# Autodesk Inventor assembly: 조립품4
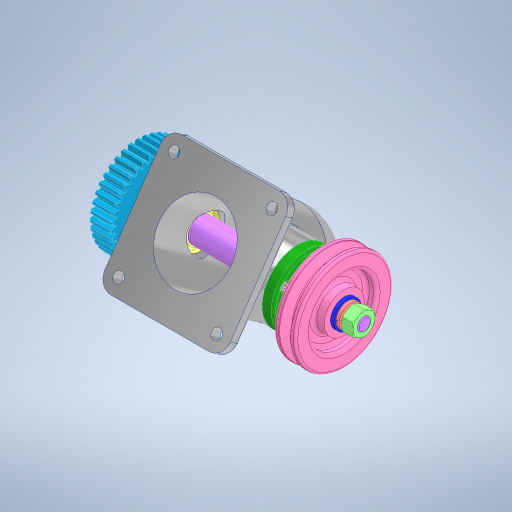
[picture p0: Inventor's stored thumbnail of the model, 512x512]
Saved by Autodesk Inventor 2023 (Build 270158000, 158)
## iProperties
Created: 2025-04
Part Number: 조립품4
Document SubType Name: Assembly
Designer: user
Author: user
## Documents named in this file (14)
- C:\Users\user\Desktop\750406V1015 유정현\OldVersions\조립품4.iam
- C:\Users\user\Desktop\750406V1015 유정현\본체.ipt
- C:\Users\user\Desktop\750406V1015 유정현\깊은 홈 볼 베어링 6203.ipt
- C:\Users\user\Desktop\750406V1015 유정현\축.ipt
- C:\Users\user\Desktop\750406V1015 유정현\커버.ipt
- C:\Users\user\Desktop\750406V1015 유정현\오일 실 26 38 8.ipt
- C:\Users\user\Desktop\750406V1015 유정현\6각 구멍붙이 볼트 M4x12.ipt
- C:\Users\user\Desktop\750406V1015 유정현\칼라.ipt
- C:\Users\user\Desktop\750406V1015 유정현\평행 키 5x5x12.ipt
- C:\Users\user\Desktop\750406V1015 유정현\스퍼기어.ipt
- C:\Users\user\Desktop\750406V1015 유정현\V 벨트 풀리.ipt
- C:\Users\user\Desktop\750406V1015 유정현\평와셔 M12.ipt
- C:\Users\user\Desktop\750406V1015 유정현\스프링 와셔 M12.ipt
- C:\Users\user\Desktop\750406V1015 유정현\6각 너트 M12x1.ipt
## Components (11 placed, 3 different names)
1. 6각 구멍붙이 볼트 M4x12:1
2. 6각 구멍붙이 볼트 M4x12:2
3. 6각 구멍붙이 볼트 M4x12:3
4. 6각 구멍붙이 볼트 M4x12:4
5. 6각 구멍붙이 볼트 M4x12:6
6. 6각 구멍붙이 볼트 M4x12:7
7. 6각 구멍붙이 볼트 M4x12:8
8. 6각 구멍붙이 볼트 M4x12:9
9. V 벨트 풀리:1
10. 6각 너트 M12x1:1
11. 6각 너트 M12x1:2
